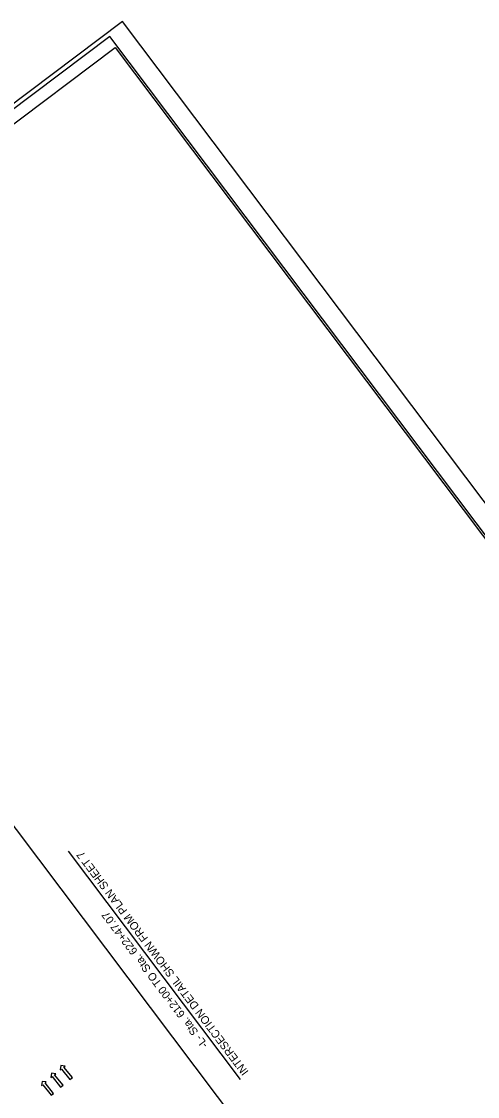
# Model space of a CAD drawing. Extents: x 1263113 to 1265001, y 775064 to 777068.
# Drawn here: x 1263883 to 1264357, y 775951 to 777068 of the extents above; entities that cross this region are included whole.
import ezdxf

# ---------------------------------------------------------------- set-up
doc = ezdxf.new("R2010")
doc.units = 0
for name, color, linetype in [('Prop Horizontal Alignment Curve and Spiral Data', 7, 'Continuous'), ('Prop Lane Arrow CELL', 7, 'Continuous'), ('Sheet Plot Border Inside CELL', 7, 'Continuous'), ('Sheet Plot Border Outside CELL', 7, 'Continuous'), ('Sheet Typical CELL', 7, 'Continuous')]:
    doc.layers.add(name, color=color, linetype=linetype)

msp = doc.modelspace()

# ---------------------------------------------------------------- linework, layer by layer
at = {"layer": 'Prop Horizontal Alignment Curve and Spiral Data'}
msp.add_line((1264110.6, 775968.4), (1263931.7, 776205.9), dxfattribs=at)
at = {"layer": 'Prop Lane Arrow CELL'}
for p, q in [((1263914.2, 775975), (1263913.6, 775970.5)), ((1263918.6, 775974.5), (1263914.2, 775975)), ((1263917.4, 775973.5), (1263918.6, 775974.5)), ((1263923.8, 775982.9), (1263923.3, 775978.4)), ((1263923.3, 775978.4), (1263924.5, 775979.4)), ((1263928.2, 775982.4), (1263923.8, 775982.9)), ((1263924.5, 775979.4), (1263933.2, 775968.4)), ((1263927.1, 775981.4), (1263928.2, 775982.4)), ((1263935.8, 775970.5), (1263927.1, 775981.4)), ((1263904.3, 775966.5), (1263903.8, 775962.1)), ((1263903.8, 775962.1), (1263905, 775963)), ((1263908.7, 775966), (1263904.3, 775966.5)), ((1263905, 775963), (1263913.7, 775952.1)), ((1263907.5, 775965.1), (1263908.7, 775966)), ((1263916.3, 775954.1), (1263907.5, 775965.1)), ((1263913.6, 775970.5), (1263914.8, 775971.5)), ((1263914.8, 775971.5), (1263923.6, 775960.5)), ((1263926.1, 775962.6), (1263917.4, 775973.5)), ((1263933.2, 775968.4), (1263935.8, 775970.5)), ((1263913.7, 775952.1), (1263916.3, 775954.1)), ((1263923.6, 775960.5), (1263926.1, 775962.6))]:
    msp.add_line(p, q, dxfattribs=at)
at = {"layer": 'Sheet Plot Border Inside CELL'}
msp.add_lwpolyline([(1264977.1, 775721.5), (1263974.7, 777052.3), (1263132, 776417.6), (1264134.4, 775086.8)], close=True, dxfattribs=at)
at = {"layer": 'Sheet Plot Border Outside CELL'}
msp.add_lwpolyline([(1263113.4, 776409.1), (1264126.2, 775064.4), (1265000.9, 775723.2), (1263988, 777067.9)], close=True, dxfattribs=at)
at = {"layer": 'Sheet Typical CELL'}
for p, q in [((1263141.5, 776409.1), (1263980.2, 777040.8)), ((1263980.2, 777040.8), (1264882.7, 775842.6))]:
    msp.add_line(p, q, dxfattribs=at)
msp.add_lwpolyline([(1263432.6, 776279.6), (1264082.6, 775416.6), (1264341.8, 775611.8), (1263691.8, 776474.8)], close=True, dxfattribs=at)

# ---------------------------------------------------------------- texts
at = {"layer": 'Prop Horizontal Alignment Curve and Spiral Data'}
for s, p in [('INTERSECTION DETAIL SHOWN FROM PLAN SHEET 7', (1264119.4, 775976.6)), ('-L- Sta. 612+00 TO Sta. 622+47.07', (1264077.2, 776004.8))]:
    msp.add_text(s, height=8.32, rotation=126.9874, dxfattribs=at).set_placement(p)

doc.saveas('drawing.dxf')
